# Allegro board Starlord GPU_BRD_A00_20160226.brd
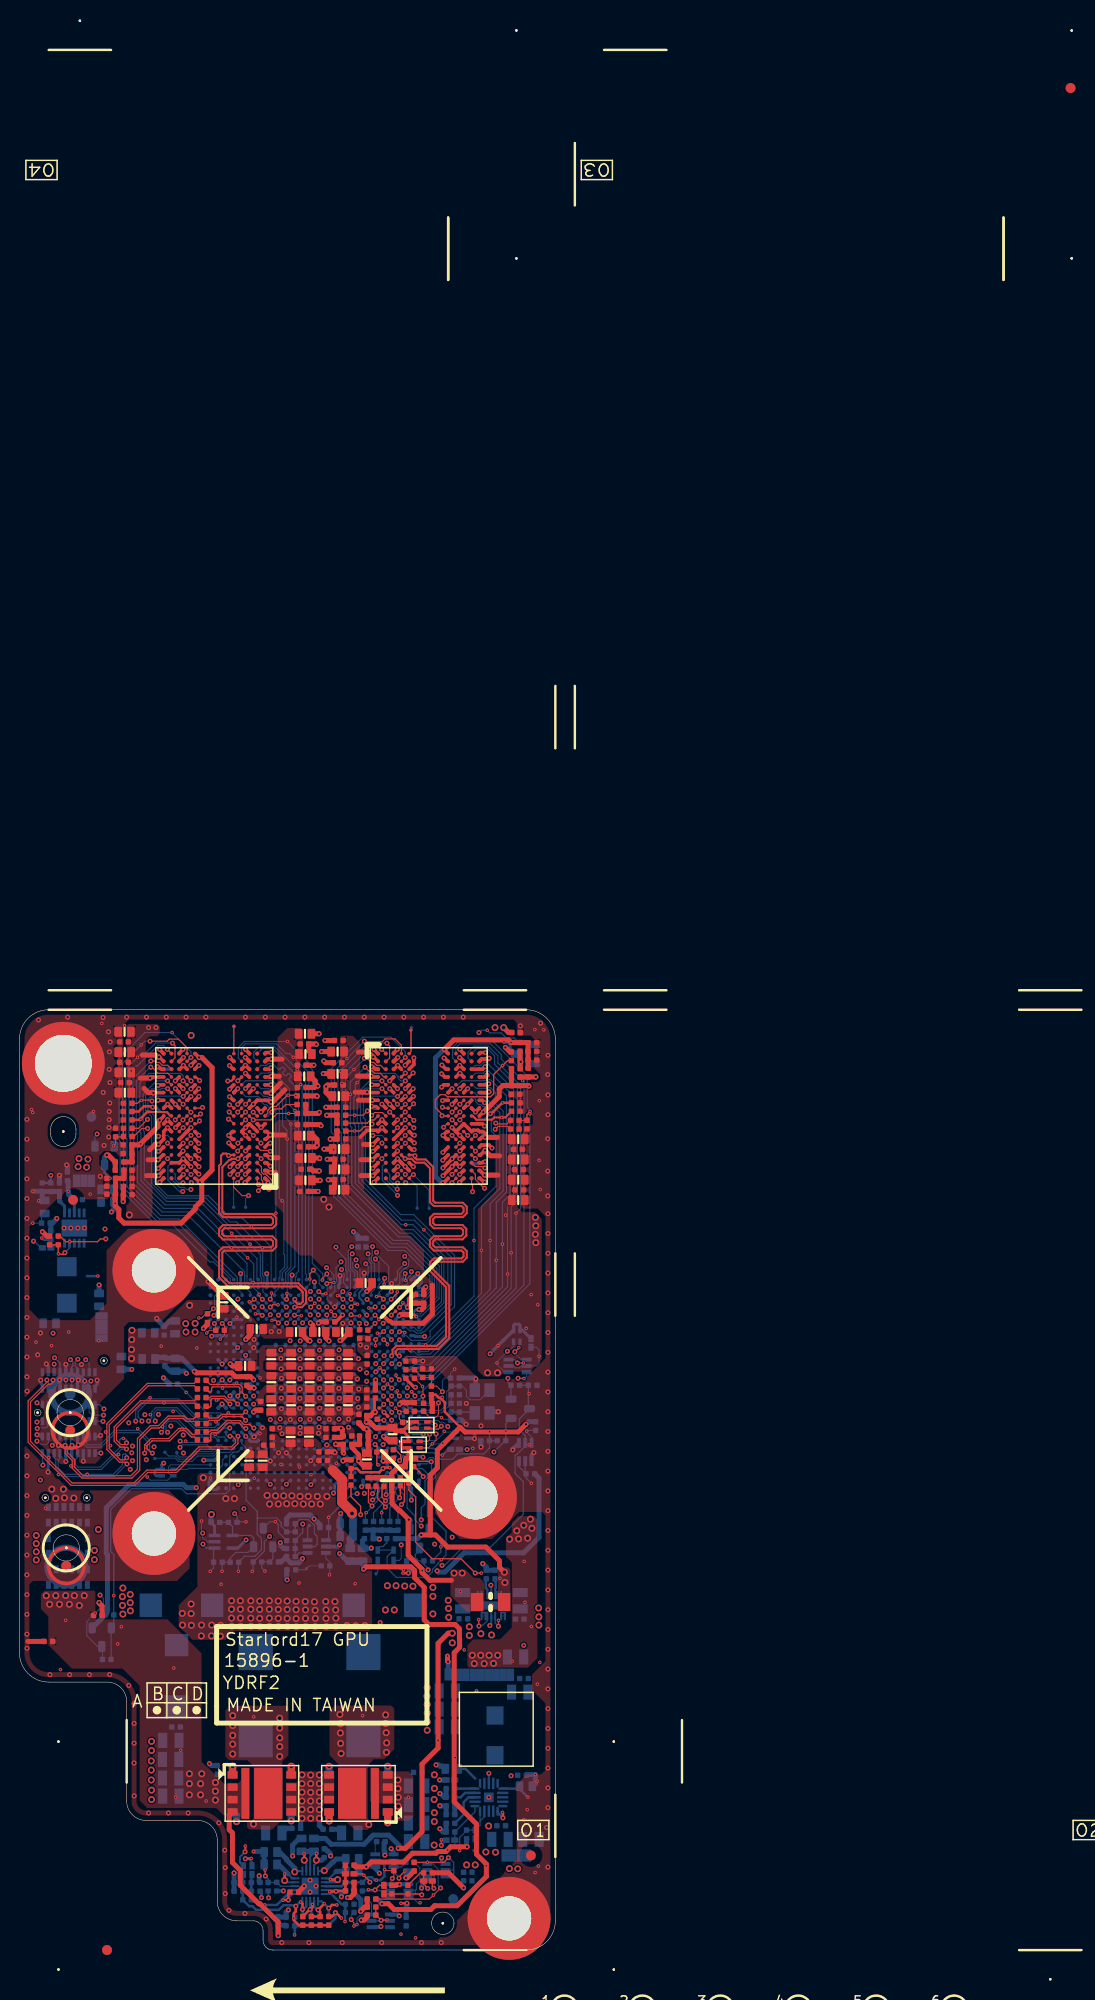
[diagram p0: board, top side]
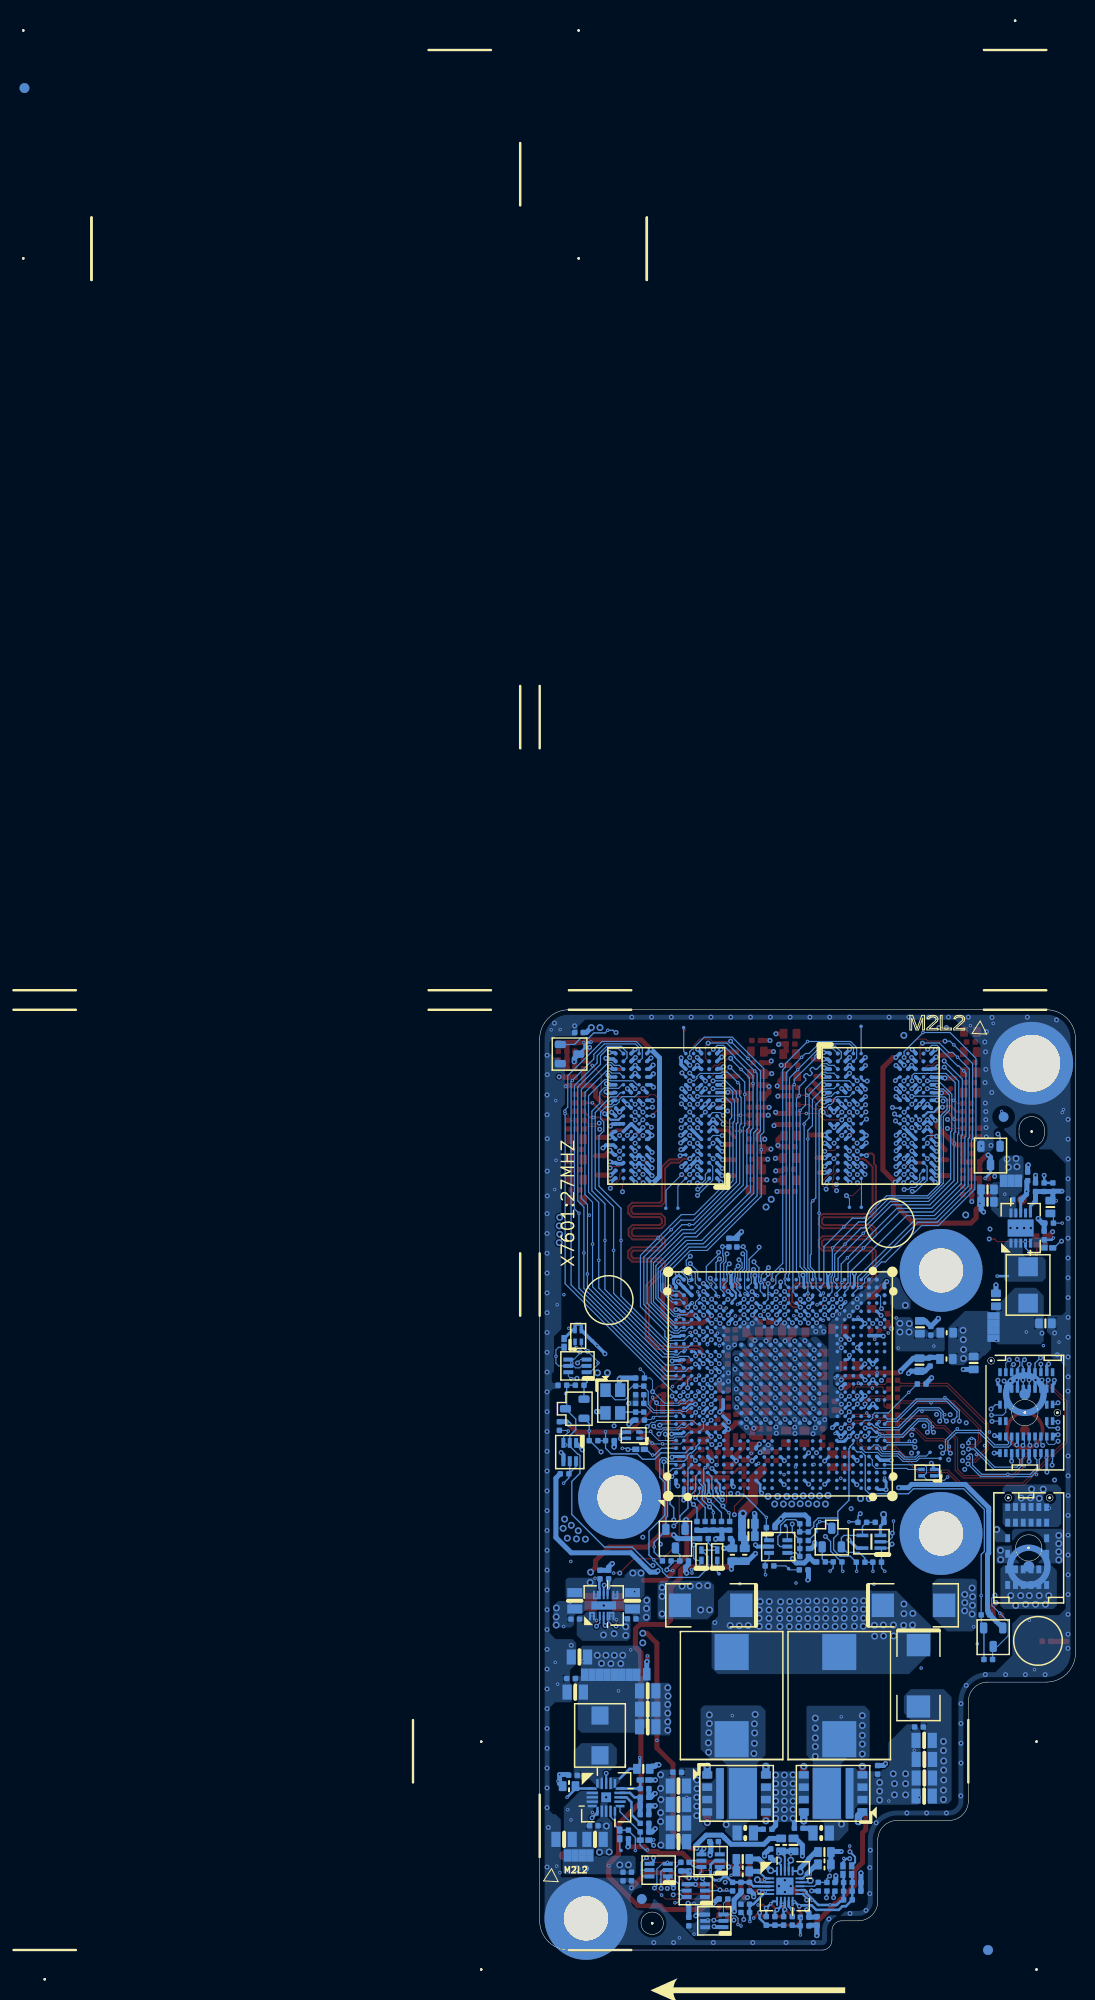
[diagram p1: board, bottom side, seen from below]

Outline 55 x 96.5 mm; copper layers: TOP, L2GND, L3, L4, L5VCC, L6, L7GND, BOTTOM. Coordinates in mm from the lower left corner of the outline.
Outline path: 0,93.5 0,30.5 arc(0.88,28.38) 3,27.5 9,27.5 arc(10.41,26.91) 11,25.5 11,15.3 arc(11.59,13.89) 13,13.3 18.3,13.3 arc(19.71,12.71) 20.3,11.3 20.3,5 arc(20.89,3.59) 22.3,3 24,3 arc(24.71,2.71) 25,2 25,1 arc(25.29,0.29) 26,0 52,0 arc(54.12,0.88) 55,3 55,93.5 arc(54.12,95.62) 52,96.5 3,96.5 arc(0.88,95.62) 0,93.5 ; 1.51,55.15 arc(1.86,55.5) 2.21,55.15 arc(1.86,54.8) 1.51,55.15 ; 1.6,91 arc(4.5,93.9) 7.4,91 arc(4.5,88.1) 1.6,91 ; 2.3,46.41 arc(2.65,46.76) 3,46.41 arc(2.65,46.06) 2.3,46.41 ; 3.2,84.25 arc(4.5,85.55) 5.8,84.25 5.8,83.75 arc(4.5,82.45) 3.2,83.75 3.2,84.25 ; 3.45,41.27 arc(4.8,42.62) 6.15,41.27 arc(4.8,39.92) 3.45,41.27 ; 3.85,55.15 arc(5.2,56.5) 6.55,55.15 arc(5.2,53.8) 3.85,55.15 ; 6.55,46.41 arc(6.9,46.76) 7.26,46.41 arc(6.9,46.06) 6.55,46.41 ; 8.31,60.48 arc(8.66,60.83) 9.01,60.48 arc(8.66,60.13) 8.31,60.48 ; 11.55,69.75 arc(13.8,72) 16.05,69.75 arc(13.8,67.5) 11.55,69.75 ; 11.55,42.75 arc(13.8,45) 16.05,42.75 arc(13.8,40.5) 11.55,42.75 ; 42.3,2.75 arc(43.45,3.9) 44.6,2.75 arc(43.45,1.6) 42.3,2.75 ; 44.55,46.45 arc(46.8,48.7) 49.05,46.45 arc(46.8,44.2) 44.55,46.45 ; 48,3.25 arc(50.25,5.5) 52.5,3.25 arc(50.25,1) 48,3.25

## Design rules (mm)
constraint set DEFAULT: min track width 0.127, pair gap 0.102
net group CLK_50R-MW: nets PEXTSTCLK_OUT PEXTSTCLK_OUT# VIDEO_CLK_XTAL_SS
net group CPU_50R-MW: nets VGA_CORE_VID
net group FBA_VREF: nets FBA_VREF_FET_H FBA_VREF_FET_L FBA_VREFC0 FBA_VREFC1 FBA_VREFD_H FBA_VREFD_L
net group OTHER_4MIL: nets 1D05V_VGA_S0_DISCHG 1D35V_VGA_S0_DISCHG 3D3V_VGA_S0_DISCHG 3V3_AON_S0_DISCHG AC_PRESENT CLKREQ_PEG#0 DGPU_PWR_EN# FB_VREF FBA_DEBUG0 FBA_DEBUG1 N12P_JTAG_TCK N12P_JTAG_TDI N12P_JTAG_TDO N12P_JTAG_TMS N12P_JTAG_TRST N12P_XTAL_OUTBUFF P2800_VGA_DXN P2800_VGA_DXP PEX_TERMP PLT_RST# PWR_1D05V_FB_R Q7601_G TESTMODE TP_VPPNC3 TP_VPPNC4 TP_VPPNC5 TP_VPPNC6 TP_VPPNC7 TP_VPPNC8 VGA_CORE_DISCHG VPP1 VPP2
net group PLATFORM: nets 1D05V_VGA_EN 1D05V_VGA_S0_PWRGD 1D35V_PGOOD 1D35V_VGA_EN 1D35V_VGA_EN# DGPU_HOLD_RST# DGPU_PWR_EN DGPU_PWR_EN_R DGPU_PWROK FBA_MF1 FBA_MF2 FBA_MF3 FBA_MF4 FBA_SEN0 FBA_SEN2 GC6_FB_EN GC6_FB_EN_GPU GPIO5_GC6_PWR_EN GPIO5_GC6_PWR_EN# GPIO5_GC6_PWR_EN_GPU GPIO5_GC6_PWR_EN_R GPIO9_ALERT GPIO10_FBVREF GPU_CLKREQ# GPU_EVENT# GPU_EVENT_GPU# GPU_PEX_RST# GPU_PEX_RST_D# GPU_PEX_RST_HOLD GPU_PEX_RST_HOLD_GPU# OVERT# OVERT_GPU# PWR_1D05V_PGOOD PWR_1D35V_EN PWR_1D35V_PGOOD PWR_LEVEL PWR_VGA_CORE_EN# STRAP0 STRAP1 STRAP2 STRAP3 STRAP4 STRAP_REF0_GND_N9 SYS_PEX_RST_MON# SYS_PEX_RST_MON_GPU# VGA_CORE_PSI VIDEO_THERM_OVERT#
net group POWER_10M: nets 3D3V_VGA_CT_1 3V3_AON_CT_2 FB_CLAM FBA_ZQ0 FBA_ZQ1 FBA_ZQ2 FBA_ZQ3 GPU_NC_F11 PWR_1D35V_BYP PWR_1D35V_IMAX PWR_VGA_CORE_EN PWR_VGA_CORE_PSI PWR_VGA_CORE_REFIN PWR_VGA_CORE_VID PWR_VGA_CORE_VREF REFIN_VREF
net group POWER_10M_POWER: nets PWR_VGA_CORE_REFADJ PWR_VGA_CORE_SS PWR_VGA_CORE_TON PWR_VGA_CORE_TON_1
net group POWER_20M: nets 3D3V_AUX_S5 GPU_PLL_VDD PWR_1D05V_FB PWR_1D35V_VFB PWR_1D35V_VFB1
net group POWER_20M_POWER: nets PWR_1D35V_BOOT PWR_1D35V_BOOT_R PWR_VGA_CORE_BOOT1 PWR_VGA_CORE_BOOT1_1 PWR_VGA_CORE_BOOT2 PWR_VGA_CORE_BOOT2_1 PWR_VGA_SNUB1 PWR_VGA_SNUB2
net group POWER_40M: nets FB_CAL_PD_VDDQ FB_CAL_PU_GND FB_CAL_TERM_GND
net group POWER_40M_POWER: nets PWR_VGA_CORE_LGATE1 PWR_VGA_CORE_LGATE2 PWR_VGA_CORE_UGATE1 PWR_VGA_CORE_UGATE2
net group POWER_160M: nets RT8812_PVCC
net group POWER_240M_POWER: nets PWR_1D05V_SVIN
net group SMBUS_50R-MWS: nets GPU_I2CA_SCL GPU_I2CA_SDA GPU_ROM_SCLK GPU_ROM_SI GPU_ROM_SO I2CB_SCL I2CB_SDA I2CC_SCL I2CC_SDA SMBC_THERM_NV SMBD_THERM_NV SML1_SMBCLK SML1_SMBDATA
net group THERM_SHUTDOWN: nets OVER_CURRENT_P8# P_H_S# PURE_HW_SHUTDOWN#
net group VRAM_CMD_45R-MWS: nets FBA_CMD0 FBA_CMD1 FBA_CMD2 FBA_CMD3 FBA_CMD4 FBA_CMD5 FBA_CMD6 FBA_CMD7 FBA_CMD8 FBA_CMD9 FBA_CMD10 FBA_CMD11 FBA_CMD12 FBA_CMD13 FBA_CMD14 FBA_CMD15 FBA_CMD16 FBA_CMD17 FBA_CMD18 FBA_CMD19 FBA_CMD20 FBA_CMD21 FBA_CMD22 FBA_CMD23 FBA_CMD24 FBA_CMD25 FBA_CMD26 FBA_CMD27 FBA_CMD28 FBA_CMD29 FBA_CMD30 FBA_CMD31
net group VRAM_DBI_45R-MWS: nets FBA_DQM0 FBA_DQM1 FBA_DQM2 FBA_DQM3 FBA_DQM4 FBA_DQM5 FBA_DQM6 FBA_DQM7
net group VRAM_DQ_45R-MW: nets FBA_CLK0_MIDPT FBA_CLK1_MIDPT FBA_D0 FBA_D1 FBA_D2 FBA_D3 FBA_D4 FBA_D5 FBA_D6 FBA_D7 FBA_D8 FBA_D9 FBA_D10 FBA_D11 FBA_D12 FBA_D13 FBA_D14 FBA_D15 FBA_D16 FBA_D17 FBA_D18 FBA_D19 FBA_D20 FBA_D21 FBA_D22 FBA_D23 FBA_D24 FBA_D25 FBA_D26 FBA_D27 FBA_D28 FBA_D29 FBA_D30 FBA_D31 FBA_D32 FBA_D33 FBA_D34 FBA_D35 FBA_D36 FBA_D37 FBA_D38 FBA_D39 FBA_D40 FBA_D41 FBA_D42 FBA_D43 FBA_D44 FBA_D45 FBA_D46 FBA_D47 FBA_D48 FBA_D49 FBA_D50 FBA_D51 FBA_D52 FBA_D53 FBA_D54 FBA_D55 FBA_D56 FBA_D57 FBA_D58 FBA_D59 FBA_D60 FBA_D61 FBA_D62 FBA_D63
net group VRAM_EDC_45R: nets FBA_EDC0 FBA_EDC1 FBA_EDC2 FBA_EDC3 FBA_EDC4 FBA_EDC5 FBA_EDC6 FBA_EDC7
net group XTAL-MW: nets 27MHZ_OUT_R

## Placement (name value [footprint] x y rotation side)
C7301  SCD22U10V2KX-1GP  [C402H22]  18.71 52.35 90 top
C7302  SCD22U10V2KX-1GP  [C402H22]  18.71 53.19 90 top
C7303  SCD22U10V2KX-1GP  [C402H22]  18.71 54.92 90 top
C7304  SCD22U10V2KX-1GP  [C402H22]  18.71 54.03 90 top
C7305  SCD22U10V2KX-1GP  [C402H22]  18.71 55.81 90 top
C7306  SCD22U10V2KX-1GP  [C402H22]  18.71 56.7 90 top
C7307  SCD22U10V2KX-1GP  [C402H22]  18.71 57.59 90 top
C7308  SCD22U10V2KX-1GP  [C402H22]  18.71 58.47 90 top
C7310  SC4D7U6D3V3KX-GP  [C603H36]  10.45 60.25 180 bottom
C7312  SC1U10V2KX-1GP  [C402H22]  24.76 55.86 180 top
C7315  SC4D7U6D3V3KX-GP  [C603H36]  24.96 50.22 0 top
C7316  SCD1U25V2KX-GP  [C402H22]  36.08 56.65 270 top
C7317  SC4D7U6D3V3KX-GP  [C603H36]  16.02 60.07 180 bottom
C7318  SCD1U16V2KX-3GP  [C402H22]  23.33 58.4 0 top
C7319  SC1U10V2KX-1GP  [C402H22]  14.93 60.38 180 bottom
C7323  SC10U6D3V3MX-GP  [C603H38]  23.15 59.95 270 top
C7324  SC4D7U6D3V3KX-GP  [C603H36]  23.56 50.22 0 top
C7326  SC22U6D3V3MX-1-GP  [C603H40]  20.95 66.48 180 top
C7501  SCD1U16V2KX-3GP  [C402H22]  35.68 60.58 0 top
C7502  SCD1U16V2KX-3GP  [C402H22]  36.08 57.48 270 top
C7505  SCD1U16V2KX-3GP  [C402H22]  31.92 64.47 90 top
C7506  SCD1U16V2KX-3GP  [C402H22]  14.85 63.55 0 bottom
C7507  SC1U6D3V3KX-2GP  [C603H36]  30.77 63.43 90 top
C7513  SC4D7U6D3V3KX-GP  [C603H36]  28.39 63.43 90 top
C7514  SC4D7U6D3V3KX-GP  [C603H36]  33.14 63.43 90 top
C7517  SC10U10V5KX-2GP  [C805H54]  50.92 30.08 270 bottom
C7518  SC22U6D3V3MX-1-GP  [C603H40]  15.97 63.91 0 bottom
C7520  SC22U6D3V3MX-1-GP  [C603H40]  24.35 63.73 270 top
C7525  SC1U6D3V3KX-2GP  [C603H36]  35.52 68.46 90 top
C7601  SCD1U16V2KX-3GP  [C402H22]  31.18 51.13 270 top
C7602  SCD1U16V2KX-3GP  [C402H22]  31.18 50.24 270 top
C7603  SC4D7U6D3V3KX-GP  [C603H36]  33.57 43.74 90 bottom
C7604  SC10U6D3V3MX-GP  [C603H38]  33.57 42.47 90 bottom
C7605  SCD1U16V2KX-3GP  [C402H22]  33.67 51.9 90 top
C7606  SC2D2U10V2KX-GP  [C402H22]  35.85 42.22 270 bottom
C7607  SC18P50V2JN-1-GP  [C402H22]  45.15 57.43 0 bottom
C7608  SC18P50V2JN-1-GP  [C402H22]  45.15 55.65 180 bottom
C7609  SC2700P50V2KX-1-GP  [C402H22]  27.85 41.2 90 bottom
C7610  SC2700P50V2KX-1-GP  [C402H22]  27.9 39.02 90 bottom
C7701  SC4D7U6D3V3KX-GP  [C603H36]  29.78 58.27 0 top
C7702  SC4D7U6D3V3KX-GP  [C603H36]  29.78 60.63 0 top
C7703  SC4D7U6D3V3KX-GP  [C603H36]  35.65 50.35 0 top
C7704  SC4D7U6D3V3KX-GP  [C603H36]  38.29 52.94 0 top
C7708  SC4D7U6D3V3KX-GP  [C603H36]  29.71 52.68 0 top
C7709  SC4D7U6D3V3KX-GP  [C603H36]  27.88 60.63 0 top
C7710  SC22U6D3V3MX-1-GP  [C603H40]  27.83 52.66 0 top
C7711  SC1U10V2KX-1GP  [C402H22]  33.67 52.76 270 top
C7712  SC1U10V2KX-1GP  [C402H22]  31.89 52.61 90 top
C7713  SC1U10V2KX-1GP  [C402H22]  31.89 53.5 90 top
C7714  SC1U10V2KX-1GP  [C402H22]  25.95 53.06 0 top
C7717  SC22U6D3V3MX-1-GP  [C603H40]  27.88 55.91 0 top
C7719  SC4D7U6D3V3KX-GP  [C603H36]  33.72 58.27 0 top
C7720  SC4D7U6D3V3KX-GP  [C603H36]  33.72 60.63 0 top
C7721  SC4D7U6D3V3KX-GP  [C603H36]  31.82 55.91 0 top
C7722  SC4D7U6D3V3KX-GP  [C603H36]  31.82 58.27 0 top
C7723  SC4D7U6D3V3KX-GP  [C603H36]  29.78 55.91 0 top
C7724  SC4D7U6D3V3KX-GP  [C603H36]  31.82 60.63 0 top
C7725  SC4D7U6D3V3KX-GP  [C603H36]  33.72 55.91 0 top
C7726  SC4D7U6D3V3KX-GP  [C603H36]  25.85 55.91 0 top
C7728  SC1U10V2KX-1GP  [C402H22]  35.35 51.95 270 top
C7729  SCD1U16V2KX-3GP  [C402H22]  35.35 52.76 270 top
C7730  SC4D7U6D3V3KX-GP  [C603H36]  25.85 58.27 0 top
C7731  SC4D7U6D3V3KX-GP  [C603H36]  25.85 60.63 0 top
C7732  SC4D7U6D3V3KX-GP  [C603H36]  27.88 58.27 0 top
C7734  SCD1U16V2KX-3GP  [C402H22]  34.84 54.54 180 top
C7735  SCD1U16V2KX-3GP  [C402H22]  25.52 51.82 90 top
C7736  SC1U10V2KX-1GP  [C402H22]  35.65 55.3 180 top
C7801  SCD01U16V2KX-3GP  [C402H22]  52.09 84.71 180 top
C7802  SC820P50V2KX-1GP  [C402H22]  52.64 93.12 90 top
C7803  SC820P50V2KX-1GP  [C402H22]  50.49 88.27 0 top
C7804  SC10U6D3V3MX-GP  [C603H38]  32.81 78.03 270 top
C7805  SC1U6D3V3KX-2GP  [C603H36]  32.81 80.11 270 top
C7806  SC1U6D3V3KX-2GP  [C603H36]  32.81 82.2 270 top
C7807  SC1U6D3V3KX-2GP  [C603H36]  32.65 92.2 270 top
C7808  SCD1U10V2KX-4GP  [C402H20]  51.3 78.01 90 top
C7809  SC1U6D3V3KX-2GP  [C603H36]  32.65 89.92 270 top
C7810  SC1U6D3V3KX-2GP  [C603H36]  51.2 79.05 90 top
C7811  SC1U6D3V3KX-2GP  [C603H36]  51.2 81.13 90 top
C7812  SC1U6D3V3KX-2GP  [C603H36]  51.2 83.21 90 top
C7813  SC10U6D3V3MX-GP  [C603H38]  32.78 87.63 270 top
C7814  SC1U6D3V3KX-2GP  [C603H36]  51.2 76.97 90 top
C7815  SCD1U10V2KX-4GP  [C402H20]  32.78 79.07 270 top
C7816  SCD1U10V2KX-4GP  [C402H20]  32.78 81.16 270 top
C7817  SCD1U10V2KX-4GP  [C402H20]  33.04 83.24 270 top
C7818  SCD1U10V2KX-4GP  [C402H20]  32.78 93.35 270 top
C7819  SCD1U10V2KX-4GP  [C402H20]  32.65 91.06 270 top
C7820  SCD1U10V2KX-4GP  [C402H20]  32.78 88.77 270 top
C7821  SCD1U10V2KX-4GP  [C402H20]  51.27 80.09 90 top
C7822  SCD1U10V2KX-4GP  [C402H20]  50.97 94.16 90 top
C7823  SCD1U10V2KX-4GP  [C402H20]  50.97 94.16 270 bottom
C7824  SCD1U10V2KX-4GP  [C402H20]  33.04 86.49 270 top
C7825  SCD1U10V2KX-4GP  [C402H20]  51.17 82.17 90 top
C7826  SC820P50V2KX-1GP  [C402H22]  52.64 91.34 90 top
C7901  SCD01U16V2KX-3GP  [C402H22]  9.86 83.9 0 top
C7902  SC820P50V2KX-1GP  [C402H22]  11.09 81.74 270 top
C7903  SC820P50V2KX-1GP  [C402H22]  9.41 77.57 270 top
C7904  SC1U6D3V3KX-2GP  [C603H36]  29.35 91.95 90 top
C7905  SC1U6D3V3KX-2GP  [C603H36]  29.35 81.28 90 top
C7906  SC1U6D3V3KX-2GP  [C603H36]  29.35 79 90 top
C7907  SC10U6D3V3MX-GP  [C603H38]  29.3 94.03 90 top
C7908  SC820P50V2KX-1GP  [C402H22]  9.41 79.2 270 top
C7909  SCD1U10V2KX-4GP  [C402H20]  28.97 90.81 90 top
C7910  SCD1U10V2KX-4GP  [C402H20]  29.22 77.85 90 top
C7911  SCD1U10V2KX-4GP  [C402H20]  28.97 88.52 90 top
C7912  SCD1U10V2KX-4GP  [C402H20]  10.73 93.2 270 top
C7913  SCD1U10V2KX-4GP  [C402H20]  10.73 91.11 270 top
C7914  SCD1U10V2KX-4GP  [C402H20]  10.83 89.03 270 top
C7915  SC1U6D3V3KX-2GP  [C603H36]  29.22 89.67 90 top
C7916  SC1U6D3V3KX-2GP  [C603H36]  10.79 94.24 270 top
C7917  SC1U6D3V3KX-2GP  [C603H36]  10.8 92.15 270 top
C7918  SC10U6D3V3MX-GP  [C603H38]  29.22 83.57 90 top
C7919  SC1U6D3V3KX-2GP  [C603H36]  10.8 90.07 270 top
C7920  SCD1U10V2KX-4GP  [C402H20]  29.25 92.99 90 top
C7921  SCD1U10V2KX-4GP  [C402H20]  29.22 82.43 90 top
C7922  SCD1U10V2KX-4GP  [C402H20]  28.97 84.71 90 top
C7923  SCD1U10V2KX-4GP  [C402H20]  29.35 80.14 90 top
C7924  SC1U6D3V3KX-2GP  [C603H36]  10.8 87.99 270 top
C7925  SCD1U10V2KX-4GP  [C402H20]  11.12 78.36 270 top
C7926  SCD1U10V2KX-4GP  [C402H20]  11.12 77.52 270 top
C8301  SC10U10V5KX-2GP  [C805H54]  45.48 35.84 180 bottom
C8302  SC470P50V2KX-3GP  [C402H22]  48.81 38.54 0 bottom
C8304  SC10U10V5KX-2GP  [C805H54]  51.4 35.84 180 bottom
C8305  SC1U10V2KX-1GP  [C402H22]  51.35 33.96 270 bottom
C8306  SC470P50V2KX-3GP  [C402H22]  47.92 38.54 0 bottom
C8307  SC1U10V2KX-1GP  [C402H22]  45.56 33.99 90 bottom
C8308  SCD1U16V2KX-3GP  [C402H22]  36.13 3.58 90 top
C8309  SC1U10V2KX-1GP  [C402H22]  41.93 7.93 90 top
C8310  SC1U10V2KX-1GP  [C402H22]  38.22 6.2 180 top
D7301  BAT54A-1-GP  [SOT23-2D4-312H44]  25.02 42.33 180 bottom
D7601  1SS400CMT2R-GP  [SOD923-10D6AKH16]  36.77 40.52 180 bottom
D7602  1SS400CMT2R-GP  [SOD923-10D6AKH16]  38.39 40.52 180 bottom
D8301  BAT54C-7-F-3-GP  [SOT23-2D4-312H48]  51.4 55.55 90 bottom
EC9701  SCD1U25V2KX-GP  [C402H22]  8.04 34.34 90 top
EC9702  SCD1U25V2KX-GP  [C402H22]  2.96 31.68 270 top
EC9703  SCD1U25V2KX-GP  [C402H22]  26.53 3 0 bottom
EC9704  SCD1U25V2KX-GP  [C402H22]  46.45 7.55 180 bottom
EC9705  SCD1U25V2KX-GP  [C402H22]  16.07 22.89 90 bottom
EC9706  SCD1U25V2KX-GP  [C402H22]  45.58 7.55 180 bottom
GPU1  N16S-GM-S-A2-GP  [BGA595M23H83]  30.3 58.1 90 bottom
GPU2  UNI-CONN28-6R-GP-U  [XBGCB5008]  4.8 41.27 90 bottom
GPU3  UNI-CONN48-6R-GP-U1  [XBGCB5009]  5.2 55.15 270 bottom
H1  HOLE335R178-GP  [HOLE335R178]  50.25 3.25 0 bottom
H2  HOLE335R229-GP  [HOLE335R229]  4.5 91 180 bottom
H3  HOLE335R178-GP  [HOLE335R178]  46.8 46.45 180 bottom
H4  HOLE335R178-GP  [HOLE335R178]  13.8 69.75 180 bottom
H5  HOLE335R178-GP  [HOLE335R178]  13.8 42.75 180 bottom
HS1  STFSR158R113H62-GP  [STFSR158R113H62]  5.2 55.15 0 top
HS2  STFSR158R113H62-GP  [STFSR158R113H62]  4.8 41.27 0 top
L7301  MHC1608S121PBP-GP  [L603H38]  13.25 60.66 90 bottom
L7501  MHC1608S300QBP-GP  [L603H38]  13.22 63.35 90 bottom
L7601  MHC1608S300QBP-GP  [L603H38]  35.22 40.57 0 bottom
L7602  MCB1608S181FBP-GP  [L603H38]  33.95 40.57 0 bottom
NOREF  *  [unnamed]  8.98 0 0 top
NOREF#2  -  [unnamed]  51 197 180 top
NOREF#3  -  [unnamed]  61 21.39 0 top
NOREF#4  -  [unnamed]  4 -2 0 top
NOREF#5  -  [unnamed]  108 197 0 top
NOREF#6  -  [unnamed]  43.45 2.75 0 top
NOREF#7  -  [#2]  26.46 -4.14 0 top
NOREF#8  -  [unnamed]  61 -2 0 top
NOREF#9  -  [#2]  21.25 -51 0 top
NOREF#10  -  [#2]  -130.26 -32.92 0 top
NOREF#11  -  [unnamed]  4 21.39 0 top
NOREF#12  -  [unnamed]  51 173.61 180 top
NOREF#13  -  [#2]  48.94 22.66 0 top
NOREF#14  -  [#2]  21.25 -51 0 top
NOREF#15  -  [#2]  109.74 12.32 0 top
NOREF#16  -  [#2]  52.74 12.32 0 top
NOREF#17  *  [unnamed]  52.49 9.71 0 top
NOREF#18  -  [#2]  16.91 26.14 0 top
NOREF#19  -  [unnamed]  6.2 198 0 top
NOREF#20  -  [unnamed]  108 173.61 180 top
NOREF#21  *  [unnamed]  5.5 76.99 0 top
NOREF#22  -  [#2]  59.26 182.68 180 top
NOREF#23  -  [#2]  2.26 182.68 180 top
NOREF#24  -  [unnamed]  4.5 84 90 top
NOREF#25  -  [#2]  47.93 -6 0 top
NOREF#26  *  [unnamed]  107.88 191.09 0 top
NOREF#27  -  [unnamed]  105.8 -3 0 top
NOREF#28  -  [#2]  21.25 -51 0 top
NOREF#29  *  [unnamed]  7.38 85.5 180 bottom
NOREF#30  -  [#2]  40.83 -4.14 180 bottom
NOREF#31  *  [unnamed]  44.52 5.24 180 bottom
NOREF#32  *  [unnamed]  107.88 191.09 180 bottom
NOREF#33  *  [unnamed]  8.98 0 180 bottom
PC8201  SCD1U16V2KX-3GP  [C402H22]  29.07 3 180 top
PC8202  SCD1U25V2KX-GP  [C402H22]  27.8 3.38 270 bottom
PC8203  SC1KP50V2KX-1GP  [C402H22]  33.9 4.7 90 bottom
PC8204  SCD01U50V2KX-1GP  [C402H22]  29.96 3 0 top
PC8205  SC47P50V2JN-3GP  [C402H22]  28.21 5.95 90 top
PC8206  SC330P50V2KX-3GP  [C402H22]  31.61 12.39 90 bottom
PC8207  SCD1U50V3KX-GP  [C603H36]  28.95 10.79 0 bottom
PC8208  SC4D7U25V5KX-GP  [C805H54]  15.53 15.8 90 bottom
PC8209  SC4D7U25V5KX-GP  [C805H54]  15.51 17.66 90 bottom
PC8210  SC10U25V5KX-GP  [C805H56]  15.51 19.56 90 bottom
PC8211  SCD1U50V3KX-GP  [C603H36]  34.15 9.35 90 bottom
PC8212  SC4D7U25V5KX-GP  [C805H54]  40.76 11.12 270 bottom
PC8213  SC4D7U25V5KX-GP  [C805H54]  40.76 13.03 270 bottom
PC8214  SC10U25V5KX-GP  [C805H56]  40.76 14.93 270 bottom
PC8215  SC10U25V5KX-GP  [C805H56]  40.76 16.84 270 bottom
PC8216  SCD1U50V3KX-GP  [C603H36]  25.77 10.06 270 bottom
PC8217  SC47P50V2JN-3GP  [C402H22]  22.47 6.04 90 bottom
PC8218  SC330P50V2KX-3GP  [C402H22]  28.41 12.5 270 bottom
PC8219  SC47P50V2JN-3GP  [C402H22]  23.36 5.15 90 bottom
PC8220  SCD1U25V2KX-GP  [C402H22]  40.88 18.24 90 bottom
PC8221  SCD1U25V2KX-GP  [C402H22]  20.31 18.49 180 bottom
PC8222  SC47P50V2JN-3GP  [C402H22]  24.25 6.04 270 bottom
PC8223  SC2700P50V2KX-1-GP  [C402H22]  31.74 3 0 top
PC8224  SC10U25V5KX-GP  [C805H56]  15.53 21.52 90 bottom
PC8225  SCD1U25V2KX-GP  [C402H22]  33.47 6.5 0 bottom
PC8226  SCD1U25V2KX-GP  [C402H22]  33.9 6.07 270 top
PC8301  SC1U6D3V2KX-GP  [C402H22]  4.92 79.4 0 bottom
PC8302  SC22P50V2GN-GP  [C402H22]  3.22 73.33 0 bottom
PC8303  SC22U6D3V3MX-1-GP  [C603H40]  3.09 64.32 90 bottom
PC8304  SC22U6D3V3MX-1-GP  [C603H40]  8.17 66.73 0 bottom
PC8305  SC22P50V2JN-4GP  [C402H22]  3.22 78.29 180 bottom
PC8306  SC10U6D3V3MX-GP  [C603H38]  9.03 78.06 270 bottom
PC8307  SC10U6D3V3MX-GP  [C603H38]  9.03 76.79 270 bottom
PC8308  SC330P50V2KX-3GP  [C402H22]  44.24 14.79 270 bottom
PC8309  SCD01U50V2KX-1GP  [C402H22]  49.44 12.75 90 bottom
PC8310  SC10U25V5KX-GP  [C805H56]  52.49 11.36 270 bottom
PC8311  SC22U6D3V5MX-2GP  [C805H58]  43.91 22.91 90 bottom
PC8312  SC680P50V3KX-1-GP  [C603]  2.58 76.25 180 bottom
PC8313  SC22U6D3V5MX-2GP  [C805H58]  43.91 24.72 90 bottom
PC8314  SCD1U16V2KX-3GP  [C402H22]  51.78 27.87 270 bottom
PC8315  SC10U25V5KX-GP  [C805H56]  49.32 11.36 90 bottom
PC8316  SCD1U16V2KX-3GP  [C402H22]  44.24 12.12 90 bottom
PC8317  SC2D2U10V3KX-1GP  [C603H36]  44.36 18.6 90 bottom
PC8318  SC1U10V2KX-1GP  [C402H22]  44.24 16.56 90 bottom
PC8319  SCD1U25V2KX-GP  [C402H22]  51.58 17.94 90 bottom
PC8320  SC22U6D3V5MX-2GP  [C805H58]  43.91 26.6 90 bottom
PC8321  SC22U6D3V5MX-2GP  [C805H58]  51.35 26.47 270 bottom
PG8301  -  [GAP-CLOSE-PWR]  5.86 78.95 90 bottom
PG8302  -  [GAP-CLOSE-PWR]  6.62 78.95 90 bottom
PG8303  -  [GAP-CLOSE-PWR]  7.38 78.95 90 bottom
PG8304  -  [GAP-CLOSE-PWR]  8.42 62.79 180 bottom
PG8305  -  [GAP-CLOSE-PWR]  8.42 63.55 180 bottom
PG8306  -  [GAP-CLOSE-PWR]  8.42 64.32 180 bottom
PG8307  -  [GAP-CLOSE-PWR]  8.42 65.08 180 bottom
PG8308  GAP-CLOSE-PWR-3-GP  [GAP-CLOSE-PWR-3]  47.34 28.25 90 bottom
PG8309  GAP-CLOSE-PWR-3-GP  [GAP-CLOSE-PWR-3]  48.1 28.25 90 bottom
PG8310  GAP-CLOSE-PWR-3-GP  [GAP-CLOSE-PWR-3]  48.86 28.25 90 bottom
PG8311  GAP-CLOSE-PWR-3-GP  [GAP-CLOSE-PWR-3]  49.62 28.25 90 bottom
PG8312  GAP-CLOSE-PWR-3-GP  [GAP-CLOSE-PWR-3]  50.38 28.25 90 bottom
PG8313  GAP-CLOSE-PWR-3-GP  [GAP-CLOSE-PWR-3]  44.01 28.3 90 bottom
PG8314  GAP-CLOSE-PWR-3-GP  [GAP-CLOSE-PWR-3]  52.14 9.71 90 bottom
PG8315  GAP-CLOSE-PWR-3-GP  [GAP-CLOSE-PWR-3]  51.37 9.71 90 bottom
PG8316  GAP-CLOSE-PWR-3-GP  [GAP-CLOSE-PWR-3]  50.61 9.71 90 bottom
PG8317  GAP-CLOSE-PWR-3-GP  [GAP-CLOSE-PWR-3]  49.85 9.71 90 bottom
PG8318  GAP-CLOSE-PWR-3-GP  [GAP-CLOSE-PWR-3]  45.81 28.25 90 bottom
PG8319  GAP-CLOSE-PWR-3-GP  [GAP-CLOSE-PWR-3]  46.57 28.25 90 bottom
PG8320  GAP-CLOSE-PWR-3-GP  [GAP-CLOSE-PWR-3]  45.05 28.25 90 bottom
PL8201  COIL-D22UH-3-GP  [L112100-2630-UH119]  35.3 26.11 0 bottom
PL8202  COIL-D22UH-3-GP  [L112100-2630-UH119]  24.25 26.11 0 bottom
PL8301  IND-2D2UH-161-GP-U  [L4240-D815-UH79]  4.87 68.25 180 bottom
PL8302  IND-D68UH-40-GP  [L4947-1015H119]  48.81 22.03 0 bottom
PQ8301  2N7002KDW-GP  [SOT-363H44]  37.07 3 90 bottom
PQ8305  2N7002KDW-GP  [SOT-363H44]  37.46 9.17 90 bottom
PQ8306  2N7002KDW-GP  [SOT-363H44]  38.98 6.1 90 bottom
PQ8307  2N7002KDW-GP  [SOT-363H44]  42.79 8.2 90 bottom
PQ8308  2N7002KDW-GP  [SOT-363H44]  51.91 51.11 0 bottom
PR8201  499KR2F-1-GP  [R402H16]  29.07 3 0 bottom
PR8202  2D2R2F-GP  [R402H16]  27.8 2.49 270 bottom
PR8203  100KR2J-1-GP  [R402H16]  26.41 6.5 0 bottom
PR8206  20KR2F-L-GP  [R402H16]  29.96 3 180 bottom
PR8207  0R2J-2-GP  [R402H16]  33.9 3.86 90 bottom
PR8208  2KR2F-3-GP  [R402H16]  30.85 3 180 bottom
PR8209  18KR2F-GP  [R402H16]  30.85 3 0 top
PR8210  0R3J-0-U-GP  [R603H22]  34.15 8.08 270 bottom
PR8211  0R3J-0-U-GP  [R603H22]  25.77 8.79 90 bottom
PR8212  100R2F-L1-GP-U  [R402H14]  24.25 6.93 90 bottom
PR8213  100R2F-L1-GP-U  [R402H14]  22.47 6.93 90 bottom
PR8215  2D2R5F-2-GP  [R805H24]  26.1 12.01 270 bottom
PR8216  2D2R5F-2-GP  [R805H24]  33.9 12.01 90 bottom
PR8220  -  [0R0402-PAD]  22.98 8.2 0 bottom
PR8221  -  [0R0402-PAD]  23.87 8.2 0 bottom
PR8222  20KR2F-L-GP  [R402H16]  31.74 3 180 bottom
PR8223  2D2R3J-2-GP  [R603H22]  30.22 10.79 180 bottom
PR8224  8K45R2F-2-GP  [R402H16]  31.28 9.93 0 bottom
PR8256  1KR2J-1-GP  [R402H16]  34.33 6.51 0 bottom
PR8257  -  [0R0402-PAD]  33.9 7.82 270 top
PR8258  10KR2J-3-GP  [R402H16]  33.9 8.71 270 top
PR8259  10KR2J-3-GP  [R402H16]  33.9 6.93 90 top
PR8260  13KR2F-GP  [R402H16]  35.19 6.51 0 bottom
PR8301  2D2R2F-GP  [R402H16]  6.01 77.02 90 bottom
PR8302  51KR2F-L-GP  [R402H16]  4.1 78.29 0 bottom
PR8303  38K3R2F-GP  [R402H16]  2.33 78.29 180 bottom
PR8304  100KR2F-L1-GP  [R402H16]  3.09 72.83 0 top
PR8306  100R2J-2-GP  [R402H14]  36.13 5.24 90 bottom
PR8307  100KR2J-1-GP  [R402H16]  39.69 2.92 180 bottom
PR8308  -  [0R0402-PAD]  2.78 72.06 270 bottom
PR8309  100R2J-2-GP  [R402H14]  37.1 11.13 90 bottom
PR8310  1KR2J-1-GP  [R402H16]  36.13 4.42 90 top
PR8311  100KR2F-L1-GP  [R402H16]  45.89 11.87 0 bottom
PR8313  18KR2F-GP  [R402H16]  2.71 74.6 270 bottom
PR8315  100KR2J-1-GP  [R402H16]  39.66 8.56 180 bottom
PR8316  100R2J-2-GP  [R402H14]  38.42 8.59 0 top
PR8317  100KR2J-1-GP  [R402H16]  40.5 8.56 180 bottom
PR8318  100R2J-2-GP  [R402H14]  36.13 5.23 90 top
PR8319  100KR2J-1-GP  [R402H16]  40.5 8.56 0 top
PR8320  0R2J-2-GP  [R402H16]  3.98 72.83 180 top
PR8321  -  [0R0402-PAD]  46.78 11.87 0 bottom
PR8322  -  [0R0402-PAD]  44.24 11.28 270 bottom
PR8323  0R2J-2-GP  [R402H16]  44.24 13.01 270 bottom
PR8324  0R3F-1-GP-U  [R603H24]  51.98 16.82 270 bottom
PR8325  -  [0R0402-PAD]  44.24 17.45 90 bottom
PR8326  12KR2F-L-GP  [R402H16]  44.24 15.68 90 bottom
PR8327  15KR2F-GP  [R402H16]  44.24 13.9 270 bottom
PR8328  100KR2J-1-GP  [R402H16]  52.44 48.87 270 bottom
PR8329  100R2J-2-GP  [R402H14]  52.97 53.78 180 bottom
PR8330  -  [0R0402-PAD]  41.93 7.09 270 top
PR8331  -  [0R0402-PAD]  37.4 6.2 0 top
PT8206  SE330U2VDM-L-GP  [CT7343H83]  16.63 35.38 90 bottom
PT8207  SE330U2VDM-L-GP  [CT7343H83]  16.12 28.14 180 bottom
PT8208  SE330U2VDM-L-GP  [CT7343H83]  37.46 35.38 270 bottom
PU8201  RT8812AGQW-GP  [QFN20-G1D75H32]  29.84 6.55 90 bottom
PU8202  FDMS3600-02-RJK0215-COLAY-GP  [PPAK-8P-G5324H44-COLAY]  34.79 16.08 270 bottom
PU8204  FDMS3600-02-RJK0215-COLAY-GP  [PPAK-8P-G5324H44-COLAY]  34.79 16.08 90 top
PU8206  FDMS3600-02-RJK0215-COLAY-GP  [PPAK-8P-G5324H44-COLAY]  24.88 16.08 270 top
PU8208  FDMS3600-02-RJK0215-COLAY-GP  [PPAK-8P-G5324H44-COLAY]  24.88 16.08 90 bottom
PU8301  RT8068AZQWID-GP-U  [DFN10G3-G265175H32]  5.63 74.1 0 bottom
PU8302  SY8288RAC-GP  [QFN20Z3-G1H36]  48.17 15.68 90 bottom
Q7301  2N7002K-2-GP  [SOT23DGS2D4H44]  8.45 32.11 0 bottom
Q7601  2N7002KDW-GP  [SOT-363H44]  51.12 59.95 90 bottom
Q7602  2N7002KDW-GP  [SOT-363H44]  30.51 41.41 270 bottom
Q7606  2N7002K-2-GP  [SOT23DGS2D4H44]  41.06 42.22 0 bottom
Q7801  2N7002K-2-GP  [SOT23DGS2D4H44]  51.93 91.95 270 bottom
Q7901  2N7002K-2-GP  [SOT23DGS2D4H44]  8.73 81.54 0 bottom
R7301  2K49R2F-GP  [R402H16]  19.29 64.85 0 top
R7302  10KR2F-2-GP  [R402H16]  15.79 58.09 90 bottom
R7303  10KR2J-3-GP  [R402H16]  9.24 34.39 90 bottom
R7304  0R2J-2-GP  [R402H16]  20.36 39.81 270 bottom
R7305  0R2J-2-GP  [R402H16]  8.96 29.82 270 bottom
R7306  100KR2F-L1-GP  [R402H16]  20.11 43.89 90 bottom
R7307  200R2F-L-GP  [R402H16]  20.59 63.6 90 top
R7308  0R2J-2-GP  [R402H16]  27.42 42.47 180 bottom
R7312  10KR2J-3-GP  [R402H16]  27.85 43.74 270 bottom
R7313  0R2J-2-GP  [R402H16]  22.06 39.81 270 bottom
R7501  60D4R2F-GP  [R402H16]  35.75 63.17 0 top
R7503  60D4R2F-GP  [R402H16]  34.92 63.22 0 top
R7505  40D2R2F-GP  [R402H16]  39.79 64.77 0 top
R7506  60D4R2F-GP  [R402H16]  41.49 66.83 0 top
R7507  42D2R2F-GP  [R402H16]  40.66 66.83 180 top
R7516  10KR2F-2-GP  [R402H16]  33.04 85.68 270 top
R7518  10KR2J-3-GP  [R402H16]  34.03 49.86 180 top
R7519  0R2J-2-GP  [R402H16]  34.03 48.16 0 top
R7520  10KR2F-2-GP  [R402H16]  35.58 72.6 180 bottom
R7521  10KR2F-2-GP  [R402H16]  34.76 72.6 180 bottom
R7524  10KR2F-2-GP  [R402H16]  28.97 85.86 90 top
R7601  10KR2J-3-GP  [R402H16]  44.69 54.38 270 bottom
R7602  10KR2J-3-GP  [R402H16]  39.69 55.73 180 top
R7603  1MR2J-1-GP  [R402H16]  44.31 57.43 180 bottom
R7604  1K3R2J-GP  [R402H16]  44.31 55.65 0 bottom
R7605  100KR2J-1-GP  [R402H16]  38.14 42.22 90 bottom
R7606  34K8R2F-1-GP  [R402H16]  41.39 59.21 180 top
R7607  40K2R2F-GP  [R402H16]  37.12 51.11 270 top
R7608  49K9R2F-L-GP  [R402H16]  38.01 43.54 180 bottom
R7609  49K9R2F-L-GP  [R402H16]  36.59 48.03 0 top
R7610  100KR2J-1-GP  [R402H16]  38.37 50.9 0 top
R7611  49K9R2F-L-GP  [R402H16]  37.18 43.54 180 bottom
R7612  10KR2J-3-GP  [R402H16]  31.28 43.36 90 bottom
R7613  10KR2J-3-GP  [R402H16]  28.31 42.47 180 bottom
R7614  49K9R2F-L-GP  [R402H16]  37.4 48.03 0 top
R7615  49K9R2F-L-GP  [R402H16]  36.34 43.54 180 bottom
R7616  20KR2F-L-GP  [R402H16]  42.28 59.21 180 top
R7617  10KR2J-3-GP  [R402H16]  39.33 53.72 180 top
R7618  10KR2F-2-GP  [R402H16]  41.93 56.11 270 top
R7619  49K9R2F-L-GP  [R402H16]  38.65 47.65 90 top
R7620  4K99R2F-L-GP  [R402H16]  41.93 55.3 270 top
R7621  4K99R2F-L-GP  [R402H16]  40.53 55.73 180 top
R7622  4K99R2F-L-GP  [R402H16]  39.66 60 180 top
R7623  0R2J-2-GP  [R402H16]  49.47 52.28 90 bottom
R7624  10KR2F-2-GP  [R402H16]  40.55 60 180 top
R7625  49K9R2F-L-GP  [R402H16]  35.78 48.03 0 top
R7626  49K9R2F-L-GP  [R402H16]  35.5 43.54 180 bottom
R7627  10KR2J-3-GP  [R402H16]  47.79 52.28 90 bottom
R7628  49K9R2F-L-GP  [R402H16]  38.65 48.47 90 top
R7629  49K9R2F-L-GP  [R402H16]  38.85 43.54 180 bottom
R7630  0R2J-2-GP  [R402H16]  24.42 39.83 270 bottom
R7631  10KR2J-3-GP  [R402H16]  26.13 39.83 90 bottom
R7632  4K99R2F-L-GP  [R402H16]  40.1 58.68 270 top
R7633  10KR2J-3-GP  [R402H16]  40.02 49.61 90 top
R7634  0R2J-2-GP  [R402H16]  21.88 43.89 90 bottom
R7635  4K99R2F-L-GP  [R402H16]  42.28 57.43 180 top
R7636  0R2J-2-GP  [R402H16]  39.97 48.36 0 top
R7637  24K9R2F-L-GP  [R402H16]  44.69 58.7 270 bottom
R7643  10KR2J-3-GP  [R402H16]  36.72 54.03 0 top
R7644  10KR2J-3-GP  [R402H16]  41.95 39.93 270 bottom
R7645  10KR2J-3-GP  [R402H16]  27.85 40.39 270 bottom
R7648  10KR2J-3-GP  [R402H16]  40.17 39.93 90 bottom
R7649  10KR2J-3-GP  [R402H16]  40.2 50.45 270 top
R7653  0R2J-2-GP  [R402H16]  31.41 39.42 90 bottom
R7656  -  [0R0402-PAD]  44.69 51.39 90 bottom
R7657  -  [0R0402-PAD]  52.49 62.31 180 bottom
R7801  40D2R2F-GP  [R402H16]  50.84 84.26 90 top
R7802  40D2R2F-GP  [R402H16]  50.84 85.14 90 top
R7803  931R2F-1-GP  [R402H16]  51.37 92.69 0 top
R7804  931R2F-1-GP  [R402H16]  50.94 90.45 90 top
R7805  549R2F-GP  [R402H16]  52.21 90.05 180 top
R7806  549R2F-GP  [R402H16]  50.94 89.59 270 top
R7807  1K33R2F-GP  [R402H16]  51.35 88.27 0 top
R7808  121R2F-GP  [R402H16]  50.94 86.94 90 top
R7809  1K33R2F-GP  [R402H16]  52.64 92.23 90 top
R7810  1KR2J-1-GP  [R402H16]  50.49 91.72 0 top
R7811  1KR2J-1-GP  [R402H16]  33.04 84.05 90 top
R7812  1KR2J-1-GP  [R402H16]  33.04 84.86 270 top
R7813  121R2F-GP  [R402H16]  50.94 86.08 90 top
R7901  1K33R2F-GP  [R402H16]  9.41 78.39 270 top
R7902  931R2F-1-GP  [R402H16]  10.28 80.88 270 top
R7903  549R2F-GP  [R402H16]  11.55 80.47 180 top
R7904  1K33R2F-GP  [R402H16]  11.09 82.63 270 top
R7905  931R2F-1-GP  [R402H16]  10.28 80.04 270 top
R7906  40D2R2F-GP  [R402H16]  11.12 84.33 270 top
R7907  549R2F-GP  [R402H16]  11.12 79.2 270 top
R7908  40D2R2F-GP  [R402H16]  11.12 83.49 270 top
R7909  1KR2J-1-GP  [R402H16]  11.12 86.9 90 top
R7910  1KR2J-1-GP  [R402H16]  28.94 86.77 90 top
R7911  1KR2J-1-GP  [R402H16]  28.94 87.66 270 top
R7912  121R2F-GP  [R402H16]  11.11 85.19 270 top
R7913  121R2F-GP  [R402H16]  11.11 86.06 270 top
R8301  0R6J-3-GP  [R1206H28]  48.35 35.72 90 top
R8303  0R2J-2-GP  [R402H16]  50.89 57.97 270 bottom
R8304  1MR2J-1-GP  [R402H16]  52.67 57.97 270 bottom
R8305  0R2J-2-GP  [R402H16]  25.52 6.5 180 bottom
R8306  0R2J-2-GP  [R402H16]  39.87 6.2 180 top
RN301  SRN1K8J-GP  [ARES2H18]  45.35 52.84 90 bottom
RN7601  SRN4K7J-8-GP  [SMD-ARES4H18]  51.04 63.02 180 bottom
RN7602  SRN10KJ-5-GP  [ARES2H18]  15.2 49 90 bottom
RN7604  SRN2K2J-1-GP  [ARES2H16]  41.27 53.88 270 top
RN7605  SRN2K2J-1-GP  [ARES2H16]  40.48 51.87 270 top
TP601  TPAD14-OP-GP  [TPAD14-OP]  37.8 54.78 0 top
TP7503  TPAD14-OP-GP  [TPAD14-OP]  38.6 65.56 0 top
TP7601  TPAD14-OP-GP  [TPAD14-OP]  14.93 51.08 180 bottom
TP7602  TPAD14-OP-GP  [TPAD14-OP]  13.88 50.45 180 bottom
TP7603  TPAD14-OP-GP  [TPAD14-OP]  37.8 56.46 0 top
TP7604  TPAD14-OP-GP  [TPAD14-OP]  36.9 55.63 0 top
TP7605  TPAD14-OP-GP  [TPAD14-OP]  16.14 51.06 180 bottom
TP7606  TPAD14-OP-GP  [TPAD14-OP]  29.76 43.56 180 bottom
TP7607  TPAD14-OP-GP  [TPAD14-OP]  29.45 39.14 180 bottom
TP7608  TPAD14-OP-GP  [TPAD14-OP]  36.59 38.61 180 bottom
TP7801  TPAD14-OP-GP  [TPAD14-OP]  40.81 76.14 0 bottom
TP7802  TPAD14-OP-GP  [TPAD14-OP]  40.22 94.67 0 bottom
TP7803  TPAD14-OP-GP  [TPAD14-OP]  40.17 94.42 180 top
TP7804  TPAD14-OP-GP  [TPAD14-OP]  42.05 76.13 0 bottom
TP7901  TPAD14-OP-GP  [TPAD14-OP]  23.21 76.23 180 bottom
TP7902  TPAD14-OP-GP  [TPAD14-OP]  22.01 94.8 0 top
TP7903  TPAD14-OP-GP  [TPAD14-OP]  22.01 94.8 180 bottom
TP7904  TPAD14-OP-GP  [TPAD14-OP]  21.99 76.23 180 bottom
TP8301  TPAD14-OP-GP  [TPAD14-OP]  46.65 10.21 180 bottom
U7301  U74LVC1G08G-AL5-R-GP-U  [SC70-5-1H44]  20.95 41.9 90 bottom
U8301  G5016KD1U-GP  [DFN14J3020-G255D85H32]  48.43 35.36 0 bottom
VRAM1  H5GQ2H24AFR-T2C-GP  [BGA170D1214H48]  42 85.6 0 bottom
VRAM2  H5GQ2H24AFR-T2C-GP  [BGA170D1214H48]  42 85.6 0 top
VRAM3  H5GQ2H24AFR-T2C-GP  [BGA170D1214H48]  20 85.6 180 top
VRAM4  H5GQ2H24AFR-T2C-GP  [BGA170D1214H48]  20 85.6 180 bottom
X7601  XTAL-27MHZ-85-GP-U  [OSC-3225-4P-4H30]  47.49 56.29 270 bottom

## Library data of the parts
C7301-C7308 = C402H22: tolerance: 78.22423.5FL
C7310 C7315 C7317 C7324 C7513 C7514 C7603 C7701-C7704 C7708 C7709 C7719-C7726 C7730-C7732 = C603H36: tolerance: 78.47520.5BL
C7312 C7319 C7711-C7714 C7728 C7736 C8305 C8307 C8309 C8310 PC8318 = C402H22: tolerance: 78.10523.5FL
C7316 EC9701-EC9706 PC8202 PC8220 PC8221 PC8225 PC8226 PC8319 = C402H22: tolerance: 78.10422.5FL
C7318 C7501 C7502 C7505 C7506 C7601 C7602 C7605 C7729 C7734 C7735 C8308 PC8201 PC8314 PC8316 = C402H22: tolerance: 78.10421.2FL
C7323 C7604 C7804 C7813 C7907 C7918 PC8306 PC8307 = C603H38: tolerance: 78.10610.5BL
C7326 C7518 C7520 C7710 C7717 PC8303 PC8304 = C603H40: tolerance: 78.22610.5BL
C7507 C7525 C7805-C7807 C7809-C7812 C7814 C7904-C7906 C7915-C7917 C7919 C7924 = C603H36: tolerance: 78.10520.2BL
C7517 C8301 C8304 = C805H54: tolerance: 78.10623.51L
C7606 = C402H22: tolerance: 78.22523.5FL
C7607 C7608 = C402H22: tolerance: 78.18034.1FL
C7609 C7610 PC8223 = C402H22: tolerance: 78.27224.2FL
C7801 C7901 = C402H22: tolerance: 78.10321.2FL
C7802 C7803 C7826 C7902 C7903 C7908 = C402H22: tolerance: 78.82124.2FL
C7808 C7815-C7825 C7909-C7914 C7920-C7923 C7925 C7926 = C402H20: tolerance: 78.10423.5FL
C8302 C8306 = C402H22: tolerance: 78.47124.2FL
D7301 = SOT23-2D4-312H44: tolerance: 75.00054.X7D
D7601 D7602 = SOD923-10D6AKH16: tolerance: 83.1S400.E2F
D8301 = SOT23-2D4-312H48: tolerance: 75.00054.E7D
GPU1 = BGA595M23H83: tolerance: 071.0N16S.0A0U
GPU2 = XBGCB5008: tolerance: 020.F0588.0028
GPU3 = XBGCB5009: tolerance: 020.F0581.0048
H1 H3-H5 = HOLE335R178: tolerance: ZZ.00PAD.7F1
H2 = HOLE335R229: tolerance: ZZ.00PAD.7G1
HS1 HS2 = STFSR158R113H62: tolerance: 434.07R01.0001
L7301 = L603H38: tolerance: 68.00335.151
L7501 L7601 = L603H38: tolerance: 68.00335.051
L7602 = L603H38: tolerance: 68.00909.261
PC8203 = C402H22: tolerance: 78.10224.2FL
PC8204 PC8309 = C402H22: tolerance: 78.10324.2FL
PC8205 PC8217 PC8219 PC8222 = C402H22: tolerance: 78.47034.1FL
PC8206 PC8218 PC8308 = C402H22: tolerance: 78.33124.2FL
PC8207 PC8211 PC8216 = C603H36: tolerance: 78.10424.2BL
PC8208 PC8209 PC8212 PC8213 = C805H54: tolerance: 78.47522.51L
PC8210 PC8214 PC8215 PC8224 PC8310 PC8315 = C805H56: tolerance: 78.10622.51L
PC8301 = C402H22: tolerance: 78.10520.5FL
PC8302 = C402H22: tolerance: 78.22044.1FL
PC8305 = C402H22: tolerance: 78.22034.1FL
PC8311 PC8313 PC8320 PC8321 = C805H58: tolerance: 78.22610.51L
PC8312 = C603: tolerance: 78.68124.2BL
PC8317 = C603H36: tolerance: 78.22523.5BL
PG8301-PG8307 = GAP-CLOSE-PWR: tolerance: ZZ.CON2D.XXX
PG8308-PG8320 = GAP-CLOSE-PWR-3: tolerance: ZZ.CLOSE.001
PL8201 PL8202 = L112100-2630-UH119: tolerance: 68.R2210.20E
PL8301 = L4240-D815-UH79: tolerance: 68.2R210.20T
PL8302 = L4947-1015H119: tolerance: 68.R6810.20E
PQ8301 PQ8305-PQ8308 Q7601 Q7602 = SOT-363H44: tolerance: 84.2N702.A3F
PR8201 = R402H16: tolerance: 64.49935.6DL
PR8202 PR8301 = R402H16: tolerance: 64.2R205.6DL
PR8203 PR8307 PR8315 PR8317 PR8319 PR8328 R7605 R7610 = R402H16: tolerance: 63.10434.1DL
PR8206 PR8222 R7616 = R402H16: tolerance: 64.20025.6DL
PR8207 PR8320 PR8323 R7304 R7305 R7308 R7313 R7519 R7623 R7630 R7634 R7636 R7653 R8303 R8305 R8306 = R402H16: tolerance: 63.R0034.1DL
PR8208 = R402H16: tolerance: 64.20015.6DL
PR8209 PR8313 = R402H16: tolerance: 64.18025.6DL
PR8210 PR8211 = R603H22: tolerance: 63.00000.00L
PR8212 PR8213 = R402H14: tolerance: 64.10005.6DL
PR8215 PR8216 = R805H24: tolerance: 64.2R205.16L
PR8220 PR8221 PR8257 PR8308 PR8321 PR8322 PR8325 PR8330 PR8331 R7656 R7657 = 0R0402-PAD: tolerance: ZZ.R0402.ZZZ
PR8223 = R603H22: tolerance: 63.2R233.15L
PR8224 = R402H16: tolerance: 64.84515.6DL
PR8256 PR8310 R7810-R7812 R7909-R7911 = R402H16: tolerance: 63.10234.1DL
PR8258 PR8259 R7303 R7312 R7518 R7601 R7602 R7612 R7613 R7617 R7627 R7631 R7633 R7643-R7645 R7648 R7649 = R402H16: tolerance: 63.10334.1DL
PR8260 = R402H16: tolerance: 64.13025.6DL
PR8302 = R402H16: tolerance: 64.51025.6DL
PR8303 = R402H16: tolerance: 64.38325.6DL
PR8304 PR8311 R7306 = R402H16: tolerance: 64.10035.6DL
PR8306 PR8309 PR8316 PR8318 PR8329 = R402H14: tolerance: 63.10134.1DL
PR8324 = R603H24: tolerance: 64.R0005.55L
PR8326 = R402H16: tolerance: 64.12025.6DL
PR8327 = R402H16: tolerance: 64.15025.6DL
PT8206-PT8208 = CT7343H83: tolerance: 79.33719.L01
PU8201 = QFN20-G1D75H32: tolerance: 74.08812.073
PU8202 PU8204 PU8206 PU8208 = PPAK-8P-G5324H44-COLAY: tolerance: ZZ.00215.037
PU8301 = DFN10G3-G265175H32: tolerance: 74.08068.A43
PU8302 = QFN20Z3-G1H36: tolerance: 074.08288.0043
Q7301 Q7606 Q7801 Q7901 = SOT23DGS2D4H44: tolerance: 84.2N702.J31
R7301 = R402H16: tolerance: 64.24915.6DL
R7302 R7516 R7520 R7521 R7524 R7618 R7624 = R402H16: tolerance: 64.10025.6DL
R7307 = R402H16: tolerance: 64.20005.6DL
R7501 R7503 R7506 = R402H16: tolerance: 64.60R45.6DL
R7505 R7801 R7802 R7906 R7908 = R402H16: tolerance: 64.40R25.6DL
R7507 = R402H16: tolerance: 64.42R25.6DL
R7603 R8304 = R402H16: tolerance: 63.10534.1DL
R7604 = R402H16: tolerance: 63.13234.1DL
R7606 = R402H16: tolerance: 64.34825.6DL
R7607 = R402H16: tolerance: 64.40225.6DL
R7608 R7609 R7611 R7614 R7615 R7619 R7625 R7626 R7628 R7629 = R402H16: tolerance: 64.49925.6DL
R7620-R7622 R7632 R7635 = R402H16: tolerance: 64.49915.6DL
R7637 = R402H16: tolerance: 64.24925.6DL
R7803 R7804 R7902 R7905 = R402H16: tolerance: 64.93105.6DL
R7805 R7806 R7903 R7907 = R402H16: tolerance: 64.54905.6DL
R7807 R7809 R7901 R7904 = R402H16: tolerance: 64.13315.6DL
R7808 R7813 R7912 R7913 = R402H16: tolerance: 64.12105.6DL
R8301 = R1206H28: tolerance: 63.R0032.11L
RN301 = ARES2H18: tolerance: 66.18236.04L
RN7601 = SMD-ARES4H18: tolerance: 66.47236.04L
RN7602 = ARES2H18: tolerance: 66.10336.04L
RN7604 RN7605 = ARES2H16: tolerance: 66.22236.04L
TP601 TP7503 TP7601-TP7608 TP7801-TP7804 TP7901-TP7904 TP8301 = TPAD14-OP: tolerance: ZZ.PAD14.001
U7301 = SC70-5-1H44: tolerance: 73.01G08.EHG
U8301 = DFN14J3020-G255D85H32: tolerance: 074.05016.0093
VRAM1-VRAM4 = BGA170D1214H48: tolerance: 72.05224.A0U
X7601 = OSC-3225-4P-4H30: tolerance: 82.30034.641

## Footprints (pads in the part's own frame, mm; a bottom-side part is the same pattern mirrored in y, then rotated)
0R0402-PAD
  custom 0.14x0.14 smd: 1(0,0.445) 2(0,-0.445)
ARES2H16
  rect 0.356x0.66 smd: 1(-0.325,-0.599) 2(0.325,-0.599) 3(0.325,0.599) 4(-0.325,0.599)
ARES2H18
  rect 0.356x0.66 smd: 1(-0.325,-0.599) 2(0.325,-0.599) 3(0.325,0.599) 4(-0.325,0.599)
BGA170D1214H48
  round 0.406 smd: A1(-5.2,6.4) A2(-4.4,6.4) A3(-3.6,6.4) A12(3.6,6.4) A13(4.4,6.4) A14(5.2,6.4) B1(-5.2,5.6) B2(-4.4,5.6) B3(-3.6,5.6) B12(3.6,5.6) B13(4.4,5.6) B14(5.2,5.6) C1(-5.2,4.8) C2(-4.4,4.8) C3(-3.6,4.8) C12(3.6,4.8) C13(4.4,4.8) C14(5.2,4.8) R1(-5.2,-4.8) R2(-4.4,-4.8) R3(-3.6,-4.8) R12(3.6,-4.8) R13(4.4,-4.8) R14(5.2,-4.8) T1(-5.2,-5.6) T2(-4.4,-5.6) T3(-3.6,-5.6) T12(3.6,-5.6) T13(4.4,-5.6) T14(5.2,-5.6) U1(-5.2,-6.4) U2(-4.4,-6.4) U3(-3.6,-6.4) U12(3.6,-6.4) U13(4.4,-6.4) U14(5.2,-6.4)
  round 0.356 smd: A4(-2.8,6.4) A5(-2,6.4) A10(2,6.4) A11(2.8,6.4) B4(-2.8,5.6) B5(-2,5.6) B10(2,5.6) B11(2.8,5.6) C4(-2.8,4.8) C5(-2,4.8) C10(2,4.8) C11(2.8,4.8) D1(-5.2,4) D2(-4.4,4) D3(-3.6,4) D4(-2.8,4) D5(-2,4) D10(2,4) D11(2.8,4) D12(3.6,4) D13(4.4,4) D14(5.2,4) E1(-5.2,3.2) E2(-4.4,3.2) E3(-3.6,3.2) E4(-2.8,3.2) E5(-2,3.2) E10(2,3.2) E11(2.8,3.2) E12(3.6,3.2) E13(4.4,3.2) E14(5.2,3.2) F1(-5.2,2.4) F2(-4.4,2.4) F3(-3.6,2.4) F4(-2.8,2.4) F5(-2,2.4) F10(2,2.4) F11(2.8,2.4) F12(3.6,2.4) F13(4.4,2.4) F14(5.2,2.4) G1(-5.2,1.6) G2(-4.4,1.6) G3(-3.6,1.6) G4(-2.8,1.6) G5(-2,1.6) G10(2,1.6) G11(2.8,1.6) G12(3.6,1.6) G13(4.4,1.6) G14(5.2,1.6) H1(-5.2,0.8) H2(-4.4,0.8) H3(-3.6,0.8) H4(-2.8,0.8) H5(-2,0.8) H10(2,0.8) H11(2.8,0.8) H12(3.6,0.8) H13(4.4,0.8) H14(5.2,0.8) J1(-5.2,0) J2(-4.4,0) J3(-3.6,0) J4(-2.8,0) J5(-2,0) J10(2,0) J11(2.8,0) J12(3.6,0) J13(4.4,0) J14(5.2,0) K1(-5.2,-0.8) K2(-4.4,-0.8) K3(-3.6,-0.8) K4(-2.8,-0.8) K5(-2,-0.8) K10(2,-0.8) K11(2.8,-0.8) K12(3.6,-0.8) K13(4.4,-0.8) K14(5.2,-0.8) L1(-5.2,-1.6) L2(-4.4,-1.6) L3(-3.6,-1.6) L4(-2.8,-1.6) L5(-2,-1.6) L10(2,-1.6) L11(2.8,-1.6) L12(3.6,-1.6) L13(4.4,-1.6) L14(5.2,-1.6) M1(-5.2,-2.4) M2(-4.4,-2.4) M3(-3.6,-2.4) M4(-2.8,-2.4) M5(-2,-2.4) M10(2,-2.4) M11(2.8,-2.4) M12(3.6,-2.4) M13(4.4,-2.4) M14(5.2,-2.4) N1(-5.2,-3.2) N2(-4.4,-3.2) N3(-3.6,-3.2) N4(-2.8,-3.2) N5(-2,-3.2) N10(2,-3.2) N11(2.8,-3.2) N12(3.6,-3.2) N13(4.4,-3.2) N14(5.2,-3.2) P1(-5.2,-4) P2(-4.4,-4) P3(-3.6,-4) P4(-2.8,-4) P5(-2,-4) P10(2,-4) P11(2.8,-4) P12(3.6,-4) P13(4.4,-4) P14(5.2,-4) R4(-2.8,-4.8) R5(-2,-4.8) R10(2,-4.8) R11(2.8,-4.8) T4(-2.8,-5.6) T5(-2,-5.6) T10(2,-5.6) T11(2.8,-5.6) U4(-2.8,-6.4) U5(-2,-6.4) U10(2,-6.4) U11(2.8,-6.4)
BGA595M23H83
  round 0.432 smd: A2(-9.9,10.7) A3(-9.1,10.7) A25(9.1,10.7) A26(9.9,10.7) AE1(-10.7,-9.1) AE2(-9.9,-9.1) AE3(-9.1,-9.1) AE25(9.1,-9.1) AE26(9.9,-9.1) AE27(10.7,-9.1) AF1(-10.7,-9.9) AF2(-9.9,-9.9) AF3(-9.1,-9.9) AF25(9.1,-9.9) AF26(9.9,-9.9) AF27(10.7,-9.9) AG2(-9.9,-10.7) AG3(-9.1,-10.7) AG25(9.1,-10.7) AG26(9.9,-10.7) B1(-10.7,9.9) B2(-9.9,9.9) B3(-9.1,9.9) B25(9.1,9.9) B26(9.9,9.9) B27(10.7,9.9) C1(-10.7,9.1) C2(-9.9,9.1) C3(-9.1,9.1) C25(9.1,9.1) C26(9.9,9.1) C27(10.7,9.1)
  round 0.381 smd: A4(-8.3,10.7) A6(-6.6,10.7) A7(-5.8,10.7) A9(-4.12,10.7) A10(-3.32,10.7) A12(-1.64,10.7) A13(-0.84,10.7) A15(0.84,10.7) A16(1.64,10.7) A18(3.32,10.7) A19(4.12,10.7) A21(5.8,10.7) A22(6.6,10.7) A24(8.3,10.7) AA1(-10.7,-5.8) AA2(-9.9,-5.8) AA3(-9.1,-5.8) AA4(-8.3,-5.8) AA5(-7.5,-5.8) AA6(-6.66,-5.8) AA7(-5.8,-5.8) AA8(-4.96,-5.8) AA9(-4.12,-5.86) AA10(-3.32,-5.86) AA12(-1.64,-5.86) AA13(-0.84,-5.86) AA14(0,-5.86) AA15(0.84,-5.86) AA16(1.64,-5.86) AA18(3.32,-5.86) AA19(4.12,-5.86) AA20(4.96,-5.8) AA21(5.8,-5.8) AA22(6.66,-5.8) AA23(7.5,-5.8) AA24(8.3,-5.8) AA25(9.1,-5.8) AA26(9.9,-5.8) AA27(10.7,-5.8) AB1(-10.7,-6.6) AB2(-9.9,-6.6) AB3(-9.1,-6.6) AB4(-8.3,-6.6) AB5(-7.5,-6.6) AB6(-6.6,-6.6) AB7(-5.8,-6.66) AB8(-4.96,-6.66) AB9(-4.12,-6.66) AB10(-3.32,-6.66) AB11(-2.48,-6.66) AB12(-1.64,-6.66) AB13(-0.84,-6.66) AB14(0,-6.66) AB15(0.84,-6.66) AB16(1.64,-6.66) AB17(2.48,-6.66) AB18(3.32,-6.66) AB19(4.12,-6.66) AB20(4.96,-6.66) AB21(5.8,-6.66) AB22(6.6,-6.6) AB23(7.5,-6.6) AB24(8.3,-6.6) AB25(9.1,-6.6) AB26(9.9,-6.6) AB27(10.7,-6.6) AC2(-9.9,-7.45) AC3(-9.1,-7.45) AC4(-8.3,-7.45) AC5(-7.45,-7.45) AC6(-6.6,-7.5) AC7(-5.8,-7.5) AC8(-4.96,-7.5) AC9(-4.12,-7.5) AC10(-3.32,-7.5) AC11(-2.48,-7.5) AC12(-1.64,-7.5) AC13(-0.84,-7.5) AC14(0,-7.5) AC15(0.84,-7.5) AC16(1.64,-7.5) AC17(2.48,-7.5) AC18(3.32,-7.5) AC19(4.12,-7.5) AC20(4.96,-7.5) AC21(5.8,-7.5) AC22(6.6,-7.5) AC23(7.45,-7.45) AC24(8.3,-7.45) AC25(9.1,-7.45) AC26(9.9,-7.45) AD1(-10.7,-8.3) AD2(-9.9,-8.3) AD3(-9.1,-8.3) AD4(-8.3,-8.3) AD5(-7.45,-8.3) AD6(-6.6,-8.3) AD7(-5.8,-8.3) AD8(-4.96,-8.3) AD9(-4.12,-8.3) AD10(-3.32,-8.3) AD11(-2.48,-8.3) AD12(-1.64,-8.3) AD13(-0.84,-8.3) AD14(0,-8.3) AD15(0.84,-8.3) AD16(1.64,-8.3) AD17(2.48,-8.3) AD18(3.32,-8.3) AD19(4.12,-8.3) AD20(4.96,-8.3) AD21(5.8,-8.3) AD22(6.6,-8.3) AD23(7.45,-8.3) AD24(8.3,-8.3) AD25(9.1,-8.3) AD26(9.9,-8.3) AD27(10.7,-8.3) AE4(-8.3,-9.1) AE5(-7.45,-9.1) AE6(-6.6,-9.1) AE7(-5.8,-9.1) AE8(-4.96,-9.1) AE9(-4.12,-9.1) AE10(-3.32,-9.1) AE11(-2.48,-9.1) AE12(-1.64,-9.1) AE13(-0.84,-9.1) AE14(0,-9.1) AE15(0.84,-9.1) AE16(1.64,-9.1) AE17(2.48,-9.1) AE18(3.32,-9.1) AE19(4.12,-9.1) AE20(4.96,-9.1) AE21(5.8,-9.1) AE22(6.6,-9.1) AE23(7.45,-9.1) AE24(8.3,-9.1) AF4(-8.3,-9.9) AF5(-7.45,-9.9) AF6(-6.6,-9.9) AF7(-5.8,-9.9) AF8(-4.96,-9.9) AF9(-4.12,-9.9) AF10(-3.32,-9.9) AF11(-2.48,-9.9) AF12(-1.64,-9.9) AF13(-0.84,-9.9) AF14(0,-9.9) AF15(0.84,-9.9) AF16(1.64,-9.9) AF17(2.48,-9.9) AF18(3.32,-9.9) AF19(4.12,-9.9) AF20(4.96,-9.9) AF21(5.8,-9.9) AF22(6.6,-9.9) AF23(7.45,-9.9) AF24(8.3,-9.9) AG4(-8.3,-10.7) AG6(-6.6,-10.7) AG7(-5.8,-10.7) AG9(-4.12,-10.7) AG10(-3.32,-10.7) AG12(-1.64,-10.7) AG13(-0.84,-10.7) AG15(0.84,-10.7) AG16(1.64,-10.7) AG18(3.32,-10.7) AG19(4.12,-10.7) AG21(5.8,-10.7) AG22(6.6,-10.7) AG24(8.3,-10.7) B4(-8.3,9.9) B5(-7.45,9.9) B6(-6.6,9.9) B7(-5.8,9.9) B8(-4.96,9.9) B9(-4.12,9.9) B10(-3.32,9.9) B11(-2.48,9.9) B12(-1.64,9.9) B13(-0.84,9.9) B14(0,9.9) B15(0.84,9.9) B16(1.64,9.9) B17(2.48,9.9) B18(3.32,9.9) B19(4.12,9.9) B20(4.96,9.9) B21(5.8,9.9) B22(6.6,9.9) B23(7.45,9.9) B24(8.3,9.9) C4(-8.3,9.1) C5(-7.45,9.1) C6(-6.6,9.1) C7(-5.8,9.1) C8(-4.96,9.1) C9(-4.12,9.1) C10(-3.32,9.1) C11(-2.48,9.1) C12(-1.64,9.1) C13(-0.84,9.1) C14(0,9.1) C15(0.84,9.1) C16(1.64,9.1) C17(2.48,9.1) C18(3.32,9.1) C19(4.12,9.1) C20(4.96,9.1) C21(5.8,9.1) C22(6.6,9.1) C23(7.45,9.1) C24(8.3,9.1) D1(-10.7,8.3) D2(-9.9,8.3) D3(-9.1,8.3) D4(-8.3,8.3) D5(-7.45,8.3) D6(-6.6,8.3) D7(-5.8,8.3) D8(-4.96,8.3) D9(-4.12,8.3) D10(-3.32,8.3) D11(-2.48,8.3) D12(-1.64,8.3) D13(-0.84,8.3) D14(0,8.3) D15(0.84,8.3) D16(1.64,8.3) D17(2.48,8.3) D18(3.32,8.3) D19(4.12,8.3) D20(4.96,8.3) D21(5.8,8.3) D22(6.6,8.3) D23(7.45,8.3) D24(8.3,8.3) D25(9.1,8.3) D26(9.9,8.3) D27(10.7,8.3) E2(-9.9,7.45) E3(-9.1,7.45) E4(-8.3,7.45) E5(-7.45,7.45) E6(-6.6,7.5) E7(-5.8,7.5) E8(-4.96,7.5) E9(-4.12,7.5) E10(-3.32,7.5) E11(-2.48,7.5) E12(-1.64,7.5) E13(-0.84,7.5) E14(0,7.5) E15(0.84,7.5) E16(1.64,7.5) E17(2.48,7.5) E18(3.32,7.5) E19(4.12,7.5) E20(4.96,7.5) E21(5.8,7.5) E22(6.6,7.5) E23(7.45,7.45) E24(8.3,7.45) E25(9.1,7.45) E26(9.9,7.45) F1(-10.7,6.6) F2(-9.9,6.6) F3(-9.1,6.6) F4(-8.3,6.6) F5(-7.5,6.6) F6(-6.6,6.6) F7(-5.8,6.66) F8(-4.96,6.66) F9(-4.12,6.66) F10(-3.32,6.66) F11(-2.48,6.66) F12(-1.64,6.66) F13(-0.84,6.66) F14(0,6.66) F15(0.84,6.66) F16(1.64,6.66) F17(2.48,6.66) F18(3.32,6.66) F19(4.12,6.66) F20(4.96,6.66) F21(5.8,6.66) F22(6.6,6.6) F23(7.5,6.6) F24(8.3,6.6) F25(9.1,6.6) F26(9.9,6.6) F27(10.7,6.6) G1(-10.7,5.8) G2(-9.9,5.8) G3(-9.1,5.8) G4(-8.3,5.8) G5(-7.5,5.8) G6(-6.66,5.8) G7(-5.8,5.8) G8(-4.96,5.8) G9(-4.12,5.86) G10(-3.32,5.86) G12(-1.64,5.86) G13(-0.84,5.86) G14(0,5.86) G15(0.84,5.86) G16(1.64,5.86) G18(3.32,5.86) G19(4.12,5.86) G20(4.96,5.8) G21(5.8,5.8) G22(6.66,5.8) G23(7.5,5.8) G24(8.3,5.8) G25(9.1,5.8) G26(9.9,5.8) G27(10.7,5.8) H2(-9.9,4.96) H3(-9.1,4.96) H4(-8.3,4.96) H5(-7.5,4.96) H6(-6.66,4.96) H22(6.66,4.96) H23(7.5,4.96) H24(8.3,4.96) H25(9.1,4.96) H26(9.9,4.96) J1(-10.7,4.12) J2(-9.9,4.12) J3(-9.1,4.12) J4(-8.3,4.12) J5(-7.5,4.12) J6(-6.66,4.12) J7(-5.86,4.12) J21(5.86,4.12) J22(6.66,4.12) J23(7.5,4.12) J24(8.3,4.12) J25(9.1,4.12) J26(9.9,4.12) J27(10.7,4.12) K1(-10.7,3.32) K2(-9.9,3.32) K3(-9.1,3.32) K4(-8.3,3.32) K5(-7.5,3.32) K6(-6.66,3.32) K7(-5.86,3.32) K21(5.86,3.32) K22(6.66,3.32) K23(7.5,3.32) K24(8.3,3.32) K25(9.1,3.32) K26(9.9,3.32) K27(10.7,3.32) L2(-9.9,2.48) L3(-9.1,2.48) L4(-8.3,2.48) L5(-7.5,2.48) L6(-6.66,2.48) L22(6.66,2.48) L23(7.5,2.48) L24(8.3,2.48) L25(9.1,2.48) L26(9.9,2.48) M1(-10.7,1.64) M2(-9.9,1.64) M3(-9.1,1.64) M4(-8.3,1.64) M5(-7.5,1.64) M6(-6.66,1.64) M7(-5.86,1.64) M21(5.86,1.64) M22(6.66,1.64) M23(7.5,1.64) M24(8.3,1.64) M25(9.1,1.64) M26(9.9,1.64) M27(10.7,1.64) N1(-10.7,0.84) N2(-9.9,0.84) N3(-9.1,0.84) N4(-8.3,0.84) N5(-7.5,0.84) N6(-6.66,0.84) N7(-5.86,0.84) N21(5.86,0.84) N22(6.66,0.84) N23(7.5,0.84) N24(8.3,0.84) N25(9.1,0.84) N26(9.9,0.84) N27(10.7,0.84) P2(-9.9,0) P3(-9.1,0) P4(-8.3,0) P5(-7.5,0) P6(-6.66,0) P22(6.66,0) P23(7.5,0) P24(8.3,0) P25(9.1,0) P26(9.9,0) R1(-10.7,-0.84) R2(-9.9,-0.84) R3(-9.1,-0.84) R4(-8.3,-0.84) R5(-7.5,-0.84) R6(-6.66,-0.84) R7(-5.86,-0.84) R21(5.86,-0.84) R22(6.66,-0.84) R23(7.5,-0.84) R24(8.3,-0.84) R25(9.1,-0.84) R26(9.9,-0.84) R27(10.7,-0.84) T1(-10.7,-1.64) T2(-9.9,-1.64) T3(-9.1,-1.64) T4(-8.3,-1.64) T5(-7.5,-1.64) T6(-6.66,-1.64) T7(-5.86,-1.64) T21(5.86,-1.64) T22(6.66,-1.64) T23(7.5,-1.64) T24(8.3,-1.64) T25(9.1,-1.64) T26(9.9,-1.64) T27(10.7,-1.64) U2(-9.9,-2.48) U3(-9.1,-2.48) U4(-8.3,-2.48) U5(-7.5,-2.48) U6(-6.66,-2.48) U22(6.66,-2.48) U23(7.5,-2.48) U24(8.3,-2.48) U25(9.1,-2.48) U26(9.9,-2.48) V1(-10.7,-3.32) V2(-9.9,-3.32) V3(-9.1,-3.32) V4(-8.3,-3.32) V5(-7.5,-3.32) V6(-6.66,-3.32) V7(-5.86,-3.32) V21(5.86,-3.32) V22(6.66,-3.32) V23(7.5,-3.32) V24(8.3,-3.32) V25(9.1,-3.32) V26(9.9,-3.32) V27(10.7,-3.32) W1(-10.7,-4.12) W2(-9.9,-4.12) W3(-9.1,-4.12) W4(-8.3,-4.12) W5(-7.5,-4.12) W6(-6.66,-4.12) W7(-5.86,-4.12) W21(5.86,-4.12) W22(6.66,-4.12) W23(7.5,-4.12) W24(8.3,-4.12) W25(9.1,-4.12) W26(9.9,-4.12) W27(10.7,-4.12) Y2(-9.9,-4.96) Y3(-9.1,-4.96) Y4(-8.3,-4.96) Y5(-7.5,-4.96) Y6(-6.66,-4.96) Y22(6.66,-4.96) Y23(7.5,-4.96) Y24(8.3,-4.96) Y25(9.1,-4.96) Y26(9.9,-4.96)
  round 0.457 smd: K10(-4,4) K11(-3,4) K12(-2,4) K13(-1,4) K14(0,4) K15(1,4) K16(2,4) K17(3,4) K18(4,4) L10(-4,3) L11(-3,3) L12(-2,3) L13(-1,3) L14(0,3) L15(1,3) L16(2,3) L17(3,3) L18(4,3) M10(-4,2) M11(-3,2) M12(-2,2) M13(-1,2) M14(0,2) M15(1,2) M16(2,2) M17(3,2) M18(4,2) N10(-4,1) N11(-3,1) N12(-2,1) N13(-1,1) N14(0,1) N15(1,1) N16(2,1) N17(3,1) N18(4,1) P10(-4,0) P11(-3,0) P12(-2,0) P13(-1,0) P14(0,0) P15(1,0) P16(2,0) P17(3,0) P18(4,0) R10(-4,-1) R11(-3,-1) R12(-2,-1) R13(-1,-1) R14(0,-1) R15(1,-1) R16(2,-1) R17(3,-1) R18(4,-1) T10(-4,-2) T11(-3,-2) T12(-2,-2) T13(-1,-2) T14(0,-2) T15(1,-2) T16(2,-2) T17(3,-2) T18(4,-2) U10(-4,-3) U11(-3,-3) U12(-2,-3) U13(-1,-3) U14(0,-3) U15(1,-3) U16(2,-3) U17(3,-3) U18(4,-3) V10(-4,-4) V11(-3,-4) V12(-2,-4) V13(-1,-4) V14(0,-4) V15(1,-4) V16(2,-4) V17(3,-4) V18(4,-4)
C402H20
  custom 0.14x0.14 smd: 1(0,0.445) 2(0,-0.445)
C402H22
  custom 0.14x0.14 smd: 1(0,0.445) 2(0,-0.445)
C603
  custom 0.197x0.197 smd: 1(0,0.66) 2(0,-0.66)
C603H36
  custom 0.197x0.197 smd: 1(0,0.66) 2(0,-0.66)
C603H38
  custom 0.197x0.197 smd: 1(0,0.66) 2(0,-0.66)
C603H40
  custom 0.197x0.197 smd: 1(0,0.66) 2(0,-0.66)
C805H54
  rect 1.549x0.94 smd: 1(0,0.838) 2(0,-0.838)
C805H56
  rect 1.549x0.94 smd: 1(0,0.838) 2(0,-0.838)
C805H58
  rect 1.549x0.94 smd: 1(0,0.838) 2(0,-0.838)
CT7343H83
  rect 2.413x2.286 smd: 1(0,3.15) 2(0,-3.15)
DFN10G3-G265175H32
  rect 0.305x0.914 smd: 1(1,1.549) 2(0.5,1.549) 3(0,1.549) 4(-0.5,1.549) 5(-1,1.549) 6(-1,-1.549) 7(-0.5,-1.549) 8(0,-1.549) 9(0.5,-1.549) 10(1,-1.549)
  rect 2.642x1.753 smd: 11(0,0)
DFN14J3020-G255D85H32
  custom 0.151x0.151 smd: 1(1.2,1.076) 6(-0.8,1.076) 8(-1.2,-1.076) 13(0.8,-1.076)
  rect 0.025x0.025 smd: 2(0.8,1.076) 7(-1.2,1.076) 9(-0.8,-1.076) 14(1.2,-1.076)
  rect 0.203x0.864 smd: 3(0.4,1.076) 4(0,1.076) 5(-0.4,1.076) 10(-0.4,-1.076) 11(0,-1.076) 12(0.4,-1.076)
  rect 2.54x0.838 smd: 15(0,0)
GAP-CLOSE-PWR
  rect 0.66x0.762 smd: 1(-0.305,0) 2(0.305,0)
GAP-CLOSE-PWR-3
  rect 0.66x0.762 smd: 1(-0.305,0) 2(0.305,0)
HOLE335R178
  round 8.509 hole 4.521: 1(0,0)
HOLE335R229
  round 8.509 hole 5.817: 1(0,0)
L603H38
  custom 0.197x0.197 smd: 1(0,0.66) 2(0,-0.66)
L4240-D815-UH79
  rect 2.007x1.956 smd: 1(0,1.872) 2(0,-1.872)
L4947-1015H119
  rect 1.753x1.88 smd: 1(0,2.045) 2(0,-2.045)
L112100-2630-UH119
  rect 3.505x3.708 smd: 1(0,4.473) 2(0,-4.473)
OSC-3225-4P-4H30
  rect 1.397x1.067 smd: 1(-1.171,-0.756) 2(1.171,-0.756) 3(1.171,0.756) 4(-1.171,0.756)
PPAK-8P-G5324H44-COLAY
  rect 0.762x1.016 smd: 1(-1.905,-3.01) 2(-0.635,-3.01) 3(0.635,-3.01) 4(1.905,-3.01) 5(1.905,3.01) 6(0.635,3.01) 7(-0.635,3.01) 8(-1.905,3.01)
  rect 5.207x2.896 smd: 9(0,0.65)
  rect 5.207x0.787 smd: 10(0,-1.7)
QFN20-G1D75H32
  rect 0.203x0.914 smd: 1(0.8,1.551) 2(0.4,1.551) 3(0,1.551) 4(-0.4,1.551) 5(-0.8,1.551) 11(-0.8,-1.551) 12(-0.4,-1.551) 13(0,-1.551) 14(0.4,-1.551) 15(0.8,-1.551)
  rect 0.914x0.203 smd: 6(-1.551,0.8) 7(-1.551,0.4) 8(-1.551,0) 9(-1.551,-0.4) 10(-1.551,-0.8) 16(1.551,-0.8) 17(1.551,-0.4) 18(1.551,0) 19(1.551,0.4) 20(1.551,0.8)
  rect 1.753x1.753 smd: 21(0,0)
QFN20Z3-G1H36
  custom 0.064x0.064 smd: 1(0.9,1.424) 5(-0.9,1.424) 6(-1.424,0.9) 10(-1.424,-0.9) 11(-0.9,-1.424) 15(0.9,-1.424) 16(1.424,-0.9) 20(1.424,0.9)
  rect 0.254x1.168 smd: 2(0.45,1.424) 3(0,1.424) 4(-0.45,1.424) 12(-0.45,-1.424) 13(0,-1.424) 14(0.45,-1.424)
  rect 1.168x0.254 smd: 7(-1.424,0.45) 8(-1.424,0) 9(-1.424,-0.45) 17(1.424,-0.45) 18(1.424,0) 19(1.424,0.45)
  rect 0.991x0.991 smd: 21(0,0)
R402H14
  custom 0.14x0.14 smd: 1(0,0.445) 2(0,-0.445)
R402H16
  custom 0.14x0.14 smd: 1(0,0.445) 2(0,-0.445)
R603H22
  custom 0.197x0.197 smd: 1(0,0.66) 2(0,-0.66)
R603H24
  custom 0.197x0.197 smd: 1(0,0.66) 2(0,-0.66)
R805H24
  rect 1.549x0.94 smd: 1(0,0.838) 2(0,-0.838)
R1206H28
  rect 1.854x1.27 smd: 1(0,1.397) 2(0,-1.397)
SC70-5-1H44
  rect 0.356x1.219 smd: 1(-0.65,-0.922) 2(0,-0.922) 3(0.65,-0.922) 4(0.65,0.921) 5(-0.65,0.921)
SMD-ARES4H18
  rect 0.356x0.66 smd: 1(-0.325,-0.599) 2(0.325,-0.599) 3(0.325,0.599) 4(-0.325,0.599)
SOD923-10D6AKH16
  rect 0.457x0.762 smd: A(0,0.527) K(0,-0.527)
